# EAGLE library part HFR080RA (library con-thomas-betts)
THOMAS&BETTS
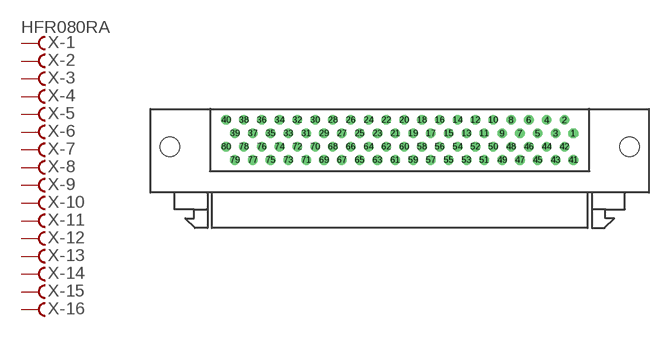
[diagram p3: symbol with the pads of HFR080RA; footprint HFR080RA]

Designator prefix X; gates -1=FV -2=F -3=F -4=F -5=F -6=F -7=F -8=F -9=F -10=F -11=F -12=F -13=F -14=F -15=F -16=F -17=F -18=F -19=F -20=F -21=F -22=F -23=F -24=F -25=F -26=F -27=F -28=F -29=F -30=F -31=F -32=F -33=F -34=F -35=F -36=F -37=F -38=F -39=F -40=F -42=F -43=F -44=F -45=F -46=F -47=F -48=F -49=F -50=F -51=F -52=F -53=F -54=F -55=F -56=F -57=F -58=F -59=F -60=F -61=F -62=F -63=F -64=F -65=F -66=F -67=F -68=F -69=F -70=F -71=F -72=F -73=F -74=F -75=F -76=F -77=F -78=F -79=F -80=F -41=F

## HFR080RA  [HFR080RA]
1  -1:F  pas
2  -2:F  pas
3  -3:F  pas
4  -4:F  pas
5  -5:F  pas
6  -6:F  pas
7  -7:F  pas
8  -8:F  pas
9  -9:F  pas
10  -10:F  pas
11  -11:F  pas
12  -12:F  pas
13  -13:F  pas
14  -14:F  pas
15  -15:F  pas
16  -16:F  pas
17  -17:F  pas
18  -18:F  pas
19  -19:F  pas
20  -20:F  pas
21  -21:F  pas
22  -22:F  pas
23  -23:F  pas
24  -24:F  pas
25  -25:F  pas
26  -26:F  pas
27  -27:F  pas
28  -28:F  pas
29  -29:F  pas
30  -30:F  pas
31  -31:F  pas
32  -32:F  pas
33  -33:F  pas
34  -34:F  pas
35  -35:F  pas
36  -36:F  pas
37  -37:F  pas
38  -38:F  pas
39  -39:F  pas
40  -40:F  pas
41  -41:F  pas
42  -42:F  pas
43  -43:F  pas
44  -44:F  pas
45  -45:F  pas
46  -46:F  pas
47  -47:F  pas
48  -48:F  pas
49  -49:F  pas
50  -50:F  pas
51  -51:F  pas
52  -52:F  pas
53  -53:F  pas
54  -54:F  pas
55  -55:F  pas
56  -56:F  pas
57  -57:F  pas
58  -58:F  pas
59  -59:F  pas
60  -60:F  pas
61  -61:F  pas
62  -62:F  pas
63  -63:F  pas
64  -64:F  pas
65  -65:F  pas
66  -66:F  pas
67  -67:F  pas
68  -68:F  pas
69  -69:F  pas
70  -70:F  pas
71  -71:F  pas
72  -72:F  pas
73  -73:F  pas
74  -74:F  pas
75  -75:F  pas
76  -76:F  pas
77  -77:F  pas
78  -78:F  pas
79  -79:F  pas
80  -80:F  pas

## Footprint HFR080RA (pad centres in mm)
THOMAS&BETTS
drill 0.864 octagon: 1 24.765,6.985
drill 0.864 round: 2 23.495,8.89; 3 22.225,6.985; 4 20.955,8.89; 5 19.685,6.985; 6 18.415,8.89; 7 17.145,6.985; 8 15.875,8.89; 9 14.605,6.985; 10 13.335,8.89; 11 12.065,6.985; 12 10.795,8.89; 13 9.525,6.985; 14 8.255,8.89; 15 6.985,6.985; 16 5.715,8.89; 17 4.445,6.985; 18 3.175,8.89; 19 1.905,6.985; 20 0.635,8.89; 21 -0.635,6.985; 22 -1.905,8.89; 23 -3.175,6.985; 24 -4.445,8.89; 25 -5.715,6.985; 26 -6.985,8.89; 27 -8.255,6.985; 28 -9.525,8.89; 29 -10.795,6.985; 30 -12.065,8.89; 31 -13.335,6.985; 32 -14.605,8.89; 33 -15.875,6.985; 34 -17.145,8.89; 35 -18.415,6.985; 36 -19.685,8.89; 37 -20.955,6.985; 38 -22.225,8.89; 39 -23.495,6.985; 40 -24.765,8.89; 41 24.765,3.175; 42 23.495,5.08; 43 22.225,3.175; 44 20.955,5.08; 45 19.685,3.175; 46 18.415,5.08; 47 17.145,3.175; 48 15.875,5.08; 49 14.605,3.175; 50 13.335,5.08; 51 12.065,3.175; 52 10.795,5.08; 53 9.525,3.175; 54 8.255,5.08; 55 6.985,3.175; 56 5.715,5.08; 57 4.445,3.175; 58 3.175,5.08; 59 1.905,3.175; 60 0.635,5.08; 61 -0.635,3.175; 62 -1.905,5.08; 63 -3.175,3.175; 64 -4.445,5.08; 65 -5.715,3.175; 66 -6.985,5.08; 67 -8.255,3.175; 68 -9.525,5.08; 69 -10.795,3.175; 70 -12.065,5.08; 71 -13.335,3.175; 72 -14.605,5.08; 73 -15.875,3.175; 74 -17.145,5.08; 75 -18.415,3.175; 76 -19.685,5.08; 77 -20.955,3.175; 78 -22.225,5.08; 79 -23.495,3.175; 80 -24.765,5.08
hole 2.769 at 32.766,5.08
hole 2.769 at -32.766,5.08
